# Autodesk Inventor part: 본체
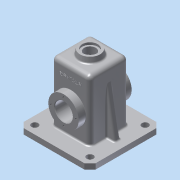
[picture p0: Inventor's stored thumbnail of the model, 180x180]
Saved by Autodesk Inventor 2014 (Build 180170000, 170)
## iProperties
Created: 2016-02
Part Number: 본체
Material: 알루미늄 6061
Document SubType Name: Modeling
Designer: SCD-A13
Density: 2.71 g/cm^3
Appearance: 알루미늄 - 평지
Mass: 1029.35 g
Surface Area: 1031.46 cm^2
Volume: 379.835 cm^3
Author: SCD-A13
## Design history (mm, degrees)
sketch "스케치1"
  geometry: C1 r 27.5 at (0, 0); 1 further point
  constraints: 1 centre point, 1 coincident
  dimensions: "d0" = 55 diameter of C1
extrude "돌출1" new body sketch "스케치1" stored distance "d1" = 96; taper "d2" = 0 deg
sketch "스케치2"
  geometry: L1 (-35, 35)-(35, 35); L2 (35, 35)-(35, -35); L3 (35, -35)-(-35, -35); L4 (-35, -35)-(-35, 35); 3 further points
  constraints: 8 end point, 2 midpoint, 2 parallel, 1 horizontal, 1 horizontal alignment, 1 perpendicular, 1 vertical alignment
  dimensions: "d3" = 70 distance of L1.start L1.end; "d4" = 70 distance of L1.end L2.end
extrude "돌출2" join sketch "스케치2" distance "d5" = 65; taper "d7" = 0 deg; dims "d6" = 55, "d8" = 0
sketch "스케치3"
  geometry: C1 r 20 at (0, 0); 1 further point
  constraints: 1 centre point, 1 coincident
  dimensions: "d9" = 40 diameter of C1
extrude "돌출3" join sketch "스케치3" distance "d10" = 10; taper "d11" = 0 deg
feature "면 기울기1" dims angle "d12" = 10 deg
sketch "스케치4"
  geometry: L1 (35, 35)-(-35, 35) reference; L2 (-35, 35)-(-35, -35) reference; L3 (-35, -35)-(35, -35) reference; L4 (35, -35)-(35, 35) reference; L5 (-65, 65)-(65, 65); L6 (65, 65)-(65, -65); L7 (65, -65)-(-65, -65); L8 (-65, -65)-(-65, 65); 3 further points
  constraints: 8 end point, 2 midpoint, 2 parallel, 1 horizontal, 1 horizontal alignment, 1 perpendicular, 1 vertical alignment
  dimensions: "d13" = 130 distance of L5.start L5.end; "d14" = 130 distance of L5.end L6.end
extrude "돌출4" join sketch "스케치4" distance "d15" = 10; taper "d16" = 0 deg
chamfer "모따기1" distance "d17" = 10; stored, may be unused: second distance "d18" = 2, angle "d19" = 45 deg
hole "구멍1" diameter "d22" = 21; stored, may be unused: countersink angle "d26" = 90 deg, drill point angle "d28" = 118 deg; dims "d20" = 10, "d21" = 10, "d23" = 6, "d24" = 28, "d25" = 4, "d27" = 8
hole "구멍2" diameter "d31" = 32; stored, may be unused: countersink angle "d35" = 90 deg, drill point angle "d37" = 118 deg; dims "d29" = 10, "d30" = 10, "d32" = 6, "d33" = 28, "d34" = 4, "d36" = 8
sketch "스케치5"
  geometry: L1 (-30, 30)-(30, 30); L2 (30, 30)-(30, -30); L3 (30, -30)-(-30, -30); L4 (-30, -30)-(-30, 30); C1 r 10.5 at (0, 0) reference; 2 further points
  constraints: 8 end point, 2 midpoint, 2 parallel, 1 horizontal, 1 horizontal alignment, 1 perpendicular, 1 vertical alignment
  dimensions: "d38" = 60 distance of L1.start L1.end; "d39" = 60 distance of L1.end L2.end
extrude "돌출5" cut sketch "스케치5" distance "d40" = 105; taper "d41" = 0 deg
sketch "스케치6"
  geometry: L1 (-65, -45)-(-35, -45) reference; L2 (-35, -45)-(-35, -27.5) reference; L3 (-35, -27.5)-(-48, -27.5) reference; L4 (-48, -27.5)-(-48, -16) reference; L5 (-48, -16)-(-30, -16) reference; L6 (-30, -16)-(-30, -55) reference; L7 (-30, -55)-(-65, -55) reference; L8 (-65, -55)-(-65, -45) reference; L9 (35, -45)-(65, -45) reference; L10 (65, -45)-(65, -55) reference; L11 (65, -55)-(30, -55) reference; L12 (30, -55)-(30, -16) reference; L13 (30, -16)-(48, -16) reference; L14 (48, -16)-(48, -27.5) reference; L15 (48, -27.5)-(35, -27.5) reference; L16 (35, -27.5)-(35, -45) reference; L17 (18.237, 75)-(20, 65) reference; L18 (20, 65)-(35, 65) reference; L19 (35, 65)-(35, 27.5) reference; L20 (35, 27.5)-(48, 27.5) reference; L21 (48, 27.5)-(48, 16) reference; L22 (48, 16)-(30, 16) reference; L23 (30, 16)-(30, 50) reference; L24 (30, 50)-(10.5, 50) reference; L25 (10.5, 50)-(10.5, 71) reference; L26 (10.5, 71)-(14, 71) reference; L27 (14, 71)-(14, 75) reference; L28 (14, 75)-(18.237, 75) reference; L29 (-35, 27.5)-(-35, 65) reference; L30 (-35, 65)-(-20, 65) reference; L31 (-20, 65)-(-18.237, 75) reference; L32 (-18.237, 75)-(-14, 75) reference; L33 (-14, 75)-(-14, 71) reference; L34 (-14, 71)-(-10.5, 71) reference; L35 (-10.5, 71)-(-10.5, 50) reference; L36 (-10.5, 50)-(-30, 50) reference; L37 (-30, 50)-(-30, 16) reference; L38 (-30, 16)-(-48, 16) reference; L39 (-48, 16)-(-48, 27.5) reference; L40 (-48, 27.5)-(-35, 27.5) reference; L41 (-30, 16)-(-23, 16); L42 (-23, 16)-(-23, 20.5); L43 (-23, 20.5)-(-30, 27.5); L44 (0, 0)-(-48, 0)
  constraints: 8 end point, 2 perpendicular, 1 parallel, 1 point on line
  dimensions: "d43" = 55 diameter of L43.end L44; "d44" = 135 deg angle of L43 L37; "d45" = 7 distance between parallel lines of L42 L37
revolve "회전1" sketch "스케치6" stored, may be unused: angle "d46" = 90 deg
sketch "스케치7"
  geometry: L1 (65, -55)-(65, 55) reference; L2 (55, 65)-(-55, 65) reference; 5 further points
  constraints: 2 horizontal alignment, 2 vertical alignment
  dimensions: "d47" = 100 distance of point (50, 50) point (-50, 50); "d48" = 15 distance from line of point (50, 50) L1; "d49" = 100 distance of point (50, -50) point (50, 50); "d50" = 15 distance from line of L2 point (50, 50)
hole "구멍3" sketch "스케치7" at (-50, 50), (50, 50), (50, -50), (-50, -50) diameter "d51" = 12; stored, may be unused: countersink angle "d55" = 90 deg, drill point angle "d57" = 118 deg; dims "d52" = 6, "d53" = 28, "d54" = 4, "d56" = 8
fillet "모깎기1" dims "d58" = 0.5
sketch "스케치8"
  geometry: C1 r 16 at (0, 0) reference; 1 further point
  constraints: 1 vertical alignment
  dimensions: "d59" = 22.5 distance of C1.centre point (0, 22.5)
hole "구멍4" sketch "스케치8" at (0, 22.5) diameter "d60" = 3.242; stored, may be unused: countersink angle "d64" = 90 deg, drill point angle "d66" = 118 deg; dims "d61" = 8, "d62" = 28, "d63" = 4, "d65" = 10
fillet "모깎기2" dims "d70" = 0.5
sketch "스케치9"
  geometry: L1 (65, 20)-(75, 18.237) reference; L2 (75, 18.237)-(75, 14) reference; L3 (75, 14)-(71, 14) reference; L4 (71, 14)-(71, 10.5) reference; L5 (71, 10.5)-(50, 10.5) reference; L6 (50, 10.5)-(50, 30) reference; L7 (50, 30)-(-55, 30) reference; L8 (-55, 30)-(-55, 65) reference; L9 (-55, 65)-(-45, 65) reference; L10 (-45, 65)-(-45, 35) reference; L11 (-45, 35)-(65, 35) reference; L12 (65, 35)-(65, 20) reference; L13 (75, -18.237)-(65, -20) reference; L14 (65, -20)-(65, -35) reference; L15 (65, -35)-(-45, -35) reference; L16 (-45, -35)-(-45, -65) reference; L17 (-45, -65)-(-55, -65) reference; L18 (-55, -65)-(-55, -30) reference; L19 (-55, -30)-(50, -30) reference; L20 (50, -30)-(50, -10.5) reference; L21 (50, -10.5)-(71, -10.5) reference; L22 (71, -10.5)-(71, -14) reference; L23 (71, -14)-(75, -14) reference; L24 (75, -14)-(75, -18.237) reference; L25 (-45, 50)-(40.069, 35); L26 (65, 20)-(75, 18.237) reference; L27 (75, 18.237)-(75, 14) reference; L28 (75, 14)-(71, 14) reference; L29 (71, 14)-(71, 10.5) reference; L30 (71, 10.5)-(50, 10.5) reference; L31 (50, 10.5)-(50, 30) reference; L32 (50, 30)-(-55, 30) reference; L33 (-55, 30)-(-55, 65) reference; L34 (-55, 65)-(-45, 65) reference; L35 (-45, 65)-(-45, 35) reference; L36 (-45, 35)-(65, 35) reference; L37 (65, 35)-(65, 20) reference; L38 (75, -18.237)-(65, -20) reference; L39 (65, -20)-(65, -35) reference; L40 (65, -35)-(-45, -35) reference; L41 (-45, -35)-(-45, -65) reference; L42 (-45, -65)-(-55, -65) reference; L43 (-55, -65)-(-55, -30) reference; L44 (-55, -30)-(50, -30) reference; L45 (50, -30)-(50, -10.5) reference; L46 (50, -10.5)-(71, -10.5) reference; L47 (71, -10.5)-(71, -14) reference; L48 (71, -14)-(75, -14) reference; L49 (75, -14)-(75, -18.237) reference; 1 further point
  constraints: 2 end point, 1 midpoint, 1 point on line
  dimensions: "d71" = 10 deg angle of L9 L25; "d97" = 15 distance from line of L25.start L9
feature "리브1" sketch "스케치9" dims "d73" = 1, "d74" = 10, "d75" = 0, "d76" = 0, "d77" = 1, "d78" = 1
sketch "스케치10"
  geometry: L1 (70, 0)-(70, -110) reference; L2 (53.237, 10)-(16.763, 10) reference; 1 further point
  constraints: 1 other
  dimensions: "d79" = 30 distance from line of point (35, -20) L2; "d80" = 35 distance from line of point (35, -20) L1
feature "엠보싱1" sketch "스케치10" dims "d1" = 96, "d81" = 0.5, "d82" = 0
fillet "모깎기5" dims "d87" = 3
fillet "모깎기6" dims "d88" = 8
fillet "모깎기7" dims "d89" = 8, "d90" = 3
fillet "모깎기8" dims "d91" = 3
chamfer "모따기2" distance "d92" = 1; stored, may be unused: second distance "d93" = 2, angle "d94" = 45 deg
fillet "모깎기9" dims "d95" = 3
fillet "모깎기10" dims "d96" = 0.5
node "솔리드1"
pattern_circular "원형 패턴1" dims angle "d68" = 360 deg
mirror "대칭1"
mirror "대칭2"
node "절단 모서리 투영1"
node "절단 모서리 투영2"
node "절단 모서리 투영3"
